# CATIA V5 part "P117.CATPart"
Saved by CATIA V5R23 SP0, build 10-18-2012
Part number: P117
Definition: Vis Chc M8x25
Description: ISO 4762 Vis Chc M8x25
Publications: "Mating Edge", "Axis"
Bounding box of the stored display mesh (mm): x -25 to 8, y -6.5 to 6.5, z -6.453 to 6.453
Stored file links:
  C:\wamp\www\COURS\CONCEPTION GMP1\TITRE 02-SEMESTRE 2\03-TP7-PRESSE MECANIQUE\eleve\P117.CATPart
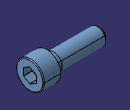
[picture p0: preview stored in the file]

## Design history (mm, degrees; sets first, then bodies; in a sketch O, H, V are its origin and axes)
Parameters
  Material = "St"
  d_dia = 8 mm
  l_nom = 25 mm
  k_head_depth_max = 8 mm
  s_nom = 6 mm
  r_min = 0.4 mm
  ds_max = 8 mm
  e = 6.86 mm
  t_min = 4 mm
  p_pitch = 1.25 mm
  Threading = 21.875 mm
  dk_max = 13 mm
  PartNumber = "ISO 4762 Vis Chc M8x35"
Body1 "PartBody" (main body)
  Sketch1 on yz-plane, origin (0, 0, 0), H (0, 1, 0), V (0, 0, 1)
    circle A1 centre (0, 0) radius 6.5
    radius A1 = 6.5 {= dk_max /2}
  Pad1: profile Sketch1, direction (1, 0, 0), length 8 {= k_head_depth_max}
  Fillet1: radius 0.4 {= r_min}, on edge [face of Pad1 | face of Pad1]
  Body2
    Sketch2 on face of Pad1, origin (8, 0, 0), H (0, 1, 0), V (0, 0, 1)
      point P1 (3, -1.7321)
      point P2 (3, 1.7321)
      point P3 (0, 3.4641)
      point P4 (-3, 1.7321)
      point P5 (-3, -1.7321)
      point P6 (0, -3.4641)
      point P7 (3, 0)
      line L1 (3, -1.7321) -> (3, 1.7321)
      line L2 (3, 1.7321) -> (0, 3.4641)
      line L3 (0, 3.4641) -> (-3, 1.7321)
      line L4 (-3, 1.7321) -> (-3, -1.7321)
      line L5 (-3, -1.7321) -> (0, -3.4641)
      line L6 (0, -3.4641) -> (3, -1.7321)
      construction line L7 (0, 0) -> (3, 0)
      construction circle A1 centre (0, 0) radius 3.4641
      construction arc A2 centre (-3, -1.7321) radius 3.4641 from (-3, 1.7321) to (0, -3.4641) cw
      construction arc A3 centre (3, 1.7321) radius 3.4641 from (0, 3.4641) to (3, -1.7321) ccw
      point P8 (-3, -1.7321)
      point P9 (3, 1.7321)
      distance L1 L4 = 6 {= s_nom}
      horizontal: L7 H
      coincidence: A1 P1, A1 P2, A1 P3, A1 P4, A1 P5, A1 P6, A2 P4, A2 P6, A2 O, P8 P5, A3 P3, A3 P1, A3 O, P9 P2
      midpoint: P7 L1
    Pad2: profile Sketch2, direction (-1, 0, 0), length 5.9769 {= t_min +(e /3.47)}
    Body3
      Sketch3 on zx-plane, origin (0, 0, 0), H (-1, 0, 0), V (0, 0, 1)
        point P1 (-2.0197, 0)
        line L1 (-2.0197, 0) -> (-4, 3.43)
        line L2 (-4, 3.43) -> (-8, 3.43)
        line L3 (-8, 3.43) -> (-8, 0)
        axis line L4 (-46.2384, 0) -> (26.3409, 0)
        reference projected line E1 (-8, -6.9227) -> (-8, 6.9227) from edge [face of Pad2 | face of Pad2]
        length L2 = 4 {= t_min}
        angle L1 L4 = 60
        distance L2 L4 = 3.43 {= e /2}
        horizontal: L2 H, L4 H
        perpendicularity: L3 L2
        fix: L4
        coincidence: L3 E1, P1 L4
      Shaft1: profile Sketch3, axis Sketch3.L4, angle 360
    Intersect1: tool Body3
  Remove1: tool Body2
  Sketch4 on xy-plane, origin (0, 0, 0), H (1, 0, 0), V (0, 1, 0)
    line L1 (0, 0) -> (0, 4)
    line L2 (0, 4) -> (-3.125, 4)
    line L3 (-3.125, 4) -> (-3.125, 3.9024)
    line L4 (-3.125, 3.9024) -> (-25, 3.9024)
    line L5 (-25, 3.9024) -> (-25, 0)
    axis line L6 (-192.3446, 0) -> (99.1594, 0)
    distance L5 L1 = 25 {= l_nom}
    distance L3 L5 = 21.875 {= Threading}
    distance L2 L6 = 4 {= ds_max /2}
    distance L4 L6 = 3.9024 {= d_dia /2.05}
    vertical: L1 V, L3 V, L5 V
    horizontal: L2 H, L4 H, L6 H
    fix: L6
  Shaft2: profile Sketch4, axis Sketch4.L6, angle 360
  Fillet2: radius 0.4 {= r_min}, on edge [face of Shaft2 | face of Pad1]
  Chamfer1: length 1.25 {= p_pitch}, angle 45, on edge [face of Shaft2 | face of Shaft2]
